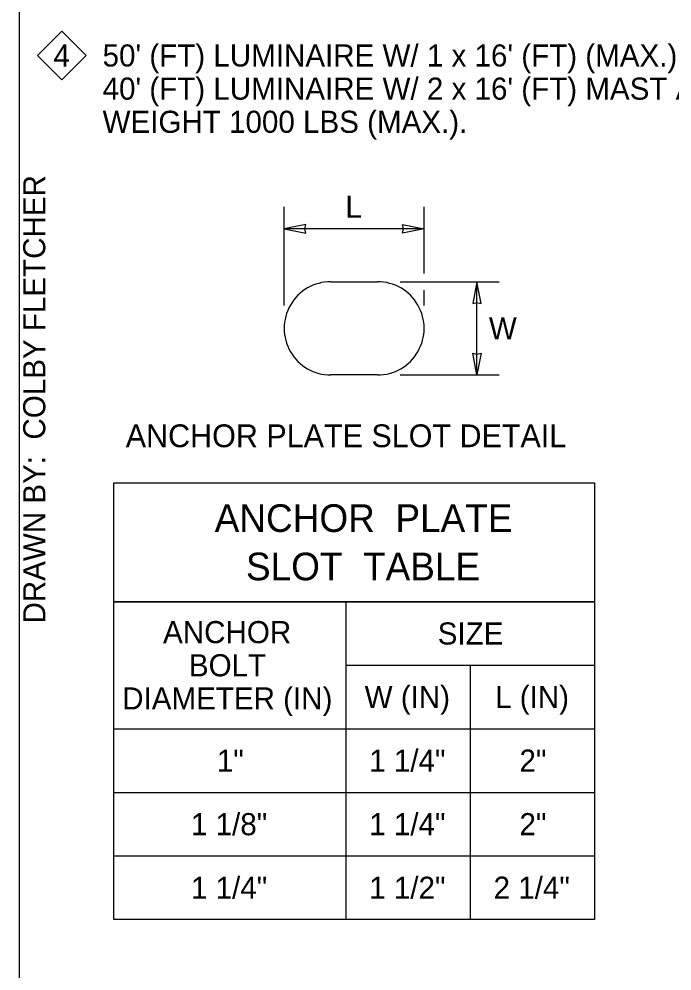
# Model space of a CAD drawing. Extents: x 99862 to 103151, y 100000 to 102076.
# Drawn here: x 99862 to 100335, y 100756 to 101445 of the extents above; entities that cross this region are included whole.
import ezdxf

# ---------------------------------------------------------------- set-up
doc = ezdxf.new("R2010")
doc.units = 0
for name, color, linetype in [('Level 1', 7, 'Continuous'), ('Level 15', 7, 'Continuous'), ('Level 20', 7, 'Continuous'), ('Level 40', 7, 'Continuous'), ('Level 5', 7, 'Continuous'), ('Level 62', 7, 'Continuous')]:
    doc.layers.add(name, color=color, linetype=linetype)

msp = doc.modelspace()

# ---------------------------------------------------------------- linework, layer by layer
at = {"layer": 'Level 1'}
msp.add_lwpolyline([(99862, 99999.5), (103151, 99999.5), (103151, 102075.5), (99862, 102075.5)], close=True, dxfattribs=at)
at = {"layer": 'Level 15'}
for p, q in [((100053.9, 101237.7), (100053.9, 101309.2)), ((100155.15, 101260.95), (100155.15, 101309.2)), ((100155.15, 101293.2), (100053.9, 101293.2)), ((100137.9, 101254.95), (100209.4, 101254.95)), ((100155.15, 101237.7), (100155.15, 101248.95)), ((100193.4, 101187.45), (100193.4, 101254.95)), ((100137.9, 101187.45), (100209.4, 101187.45))]:
    msp.add_line(p, q, dxfattribs=at)
for points in [[(100053.9, 101293.2), (100069.62, 101290.12), (100068.89, 101293.2), (100069.62, 101296.29)], [(100155.15, 101293.2), (100139.42, 101290.12), (100140.15, 101293.2), (100139.42, 101296.29)], [(100193.4, 101254.95), (100190.31, 101239.23), (100193.4, 101239.95), (100196.48, 101239.23)], [(100193.4, 101187.45), (100190.31, 101203.18), (100193.4, 101202.45), (100196.48, 101203.18)]]:
    msp.add_lwpolyline(points, close=True, dxfattribs=at)
at = {"layer": 'Level 20'}
msp.add_lwpolyline([(99892.92, 101436.24), (99910.47, 101418.69), (99892.92, 101401.13), (99875.36, 101418.69)], close=True, dxfattribs=at)
at = {"layer": 'Level 40'}
for p, q in [((99930.52, 101023.37), (100278.52, 101023.37)), ((100098.52, 101023.37), (100098.52, 100793.37)), ((100098.52, 100977.37), (100278.52, 100977.37)), ((100188.52, 100977.37), (100188.52, 100793.37)), ((99930.52, 100931.37), (100278.52, 100931.37)), ((99930.52, 100885.37), (100278.52, 100885.37)), ((99930.52, 100839.37), (100278.52, 100839.37))]:
    msp.add_line(p, q, dxfattribs=at)
msp.add_lwpolyline([(99930.52, 101109.37), (100278.52, 101109.37), (100278.52, 101023.37), (99930.52, 101023.37)], close=True, dxfattribs=at)
msp.add_lwpolyline([(100278.52, 101023.37), (100278.52, 100793.37), (99930.52, 100793.37), (99930.52, 101023.37)], dxfattribs=at)
at = {"layer": 'Level 5'}
for p, q in [((100087.65, 101254.95), (100121.4, 101254.95)), ((100121.4, 101187.45), (100087.65, 101187.45))]:
    msp.add_line(p, q, dxfattribs=at)
for centre, start, end in [((100087.65, 101221.2), 89.99954, 270.00013), ((100121.4, 101221.2), 269.99901, 90.00075)]:
    msp.add_arc(centre, 33.75, start, end, dxfattribs=at)

# ---------------------------------------------------------------- texts
at = {"layer": 'Level 20'}
for s, height, p in [('4', 16, (99886.93, 101410.69)), ("50' (FT) LUMINAIRE W/ 1 x 16' (FT) (MAX.) MAST ARM OR ", 16, (99922.47, 101410.69)), ("40' (FT) LUMINAIRE W/ 2 x 16' (FT) MAST ARMS - TOTAL", 16, (99922.47, 101386.69)), ('WEIGHT 1000 LBS (MAX.).', 16, (99922.47, 101362.69)), ('ANCHOR PLATE SLOT DETAIL', 16.5, (99939.23, 101135.2)), ('ANCHOR  PLATE', 20, (100003.6, 101073.87)), ('SLOT  TABLE', 20, (100026.24, 101038.87)), ('ANCHOR', 16, (99966.23, 100993.37)), ('SIZE', 16, (100164.98, 100992.38)), ('BOLT', 16, (99984.94, 100969.37)), ('DIAMETER (IN)', 16, (99936.65, 100945.37)), ('W (IN)', 16, (100112.14, 100946.38)), ('L (IN)', 16, (100206.52, 100946.38)), ('1"', 16, (100005.16, 100900.38)), ('1 1/4"', 16, (100115.44, 100900.38)), ('2"', 16, (100224.16, 100900.38)), ('1 1/8"', 16, (99986.44, 100854.38)), ('1 1/4"', 16, (100115.44, 100854.38)), ('2"', 16, (100224.16, 100854.38)), ('1 1/4"', 16, (99986.44, 100808.38)), ('1 1/2"', 16, (100115.44, 100808.38)), ('2 1/4"', 16, (100205.44, 100808.38))]:
    msp.add_text(s, height=height, dxfattribs=at).set_placement(p)
for s, p in [('L', (100098.18, 101301.2)), ('W', (100202.03, 101213.2))]:
    msp.add_text(s, height=16, rotation=360, dxfattribs=at).set_placement(p)
at = {"layer": 'Level 62'}
msp.add_text('DRAWN BY:  COLBY FLETCHER', height=16, rotation=90, dxfattribs=at).set_placement((99881, 101007.58))

doc.saveas('drawing.dxf')
